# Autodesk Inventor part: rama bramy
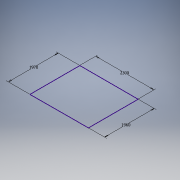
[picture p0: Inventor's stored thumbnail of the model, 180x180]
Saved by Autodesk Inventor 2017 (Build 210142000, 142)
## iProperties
Created: 2020-09
Part Number: rama bramy
Material: Generic
Document SubType Name: Modeling
Designer: X
Density: 1 g/cm^3
Appearance: Default
Author: X
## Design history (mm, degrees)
sketch "Szkic1"
  geometry: L1 (0, 0)-(0, 1970); L2 (0, 1970)-(2300, 1970); L3 (2300, 1970)-(2300, 10); L4 (0, 0)-(2300, 10)
  constraints: 8 end point, 2 vertical, 1 horizontal
  dimensions: "d6" = 1970 dimension on L1.start L1.end L1 L2.end L2 L3.end L3 L4; "d6" = 1970 distance of L1.start L1.end; "d7" = 2300 distance of L2.end L1.end; "d8" = 1960 distance of L3.end L2.end
